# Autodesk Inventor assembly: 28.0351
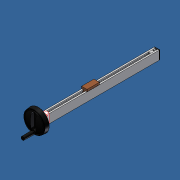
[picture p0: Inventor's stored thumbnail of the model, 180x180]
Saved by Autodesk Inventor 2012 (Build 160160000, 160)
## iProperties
Created: 2011-09
Part Number: 28.0351
Document SubType Name: Assembly
Designer: Administrator
Description: MINI ADJ UNIT 19X32
Author: Administrator
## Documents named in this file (8)
- C:\Andys Backup Data\ANDY'S INVENTOR\INVENTOR LIBRARIES\PARTS LIBRARY\READY FOR USE MODULES LG\28.0351 MINI ADJ UNIT 19X32.iam
- C:\Andys Backup Data\ANDY'S INVENTOR\INVENTOR LIBRARIES\PARTS LIBRARY\FASTENING ELEMENTS\SCREWS CAP\21.1200 M8X16.ipt
- C:\Andys Backup Data\ANDY'S INVENTOR\INVENTOR LIBRARIES\PARTS LIBRARY\READY FOR USE MODULES LG\28.0350 MINI ADJ UNIT FITTING KIT.iam
- C:\Andys Backup Data\ANDY'S INVENTOR\INVENTOR LIBRARIES\PARTS LIBRARY\READY FOR USE MODULES LG\SUBCOMPONENTS\28.0212 HANDWHEEL 80mm.iam
- C:\Andys Backup Data\ANDY'S INVENTOR\INVENTOR LIBRARIES\PARTS LIBRARY\READY FOR USE MODULES LG\SUBCOMPONENTS\19.0100_6 BUSHING.ipt
- C:\Andys Backup Data\ANDY'S INVENTOR\INVENTOR LIBRARIES\PARTS LIBRARY\READY FOR USE MODULES LG\SUBCOMPONENTS\28.0365 MINI ADJ BEARING SUPPORT 19X32.ipt
- C:\Andys Backup Data\ANDY'S INVENTOR\INVENTOR LIBRARIES\PARTS LIBRARY\READY FOR USE MODULES LG\SUBCOMPONENTS\28.0351_1 MINI ADJ 19X32 PROFILE.ipt
- C:\Andys Backup Data\ANDY'S INVENTOR\INVENTOR LIBRARIES\PARTS LIBRARY\END CAPS\22.1060_1 END CAP 19X32 GRAY.ipt
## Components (7 placed, 7 different names)
1. 21.1200 M8 x 16:1 — Insert:1
2. 28.0350 MINI ADJ UNIT FITTING KIT:1 [sub-assembly] — Mate:5, Mate:8, Angle:4, Insert:2
3. 28.0212 HANDWHEEL 80mm:1 [sub-assembly] — Mate:5, Angle:2, Mate:6, Mate:7
4. 19.0100_6 BUSHING:1 — Angle:2, Mate:6, Mate:7, Mate:8
5. 28.0365 MINI ADJ BEARING SUPPORT 19X32:1 — Mate:11, Mate:12, Angle:3, Insert:1, Insert:2
6. 28.0351_1 MINI ADJ 19X32 PROFILE:1 — Mate:9, Flush:1, Mate:10, Mate:11, Mate:12, Angle:3, Angle:4, Insert:3, Angle:5
7. 22.1060_1 END CAP 19X32 GRAY:1 — Insert:3, Angle:5
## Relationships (16: Mate 8, Angle 4, Insert 3, Flush 1)
- Mate:5: 28.0350 MINI ADJ UNIT FITTING KIT:1 ↔ 28.0212 HANDWHEEL 80mm:1
- Angle:2: 28.0212 HANDWHEEL 80mm:1 ↔ 19.0100_6 BUSHING:1
- Mate:6: 28.0212 HANDWHEEL 80mm:1 ↔ 19.0100_6 BUSHING:1
- Mate:7: 28.0212 HANDWHEEL 80mm:1 ↔ 19.0100_6 BUSHING:1
- Mate:8: 28.0350 MINI ADJ UNIT FITTING KIT:1 ↔ 19.0100_6 BUSHING:1
- Mate:9: 28.0351_1 MINI ADJ 19X32 PROFILE:1
- Flush:1: 28.0351_1 MINI ADJ 19X32 PROFILE:1
- Mate:10: 28.0351_1 MINI ADJ 19X32 PROFILE:1
- Mate:11: 28.0365 MINI ADJ BEARING SUPPORT 19X32:1 ↔ 28.0351_1 MINI ADJ 19X32 PROFILE:1
- Mate:12: 28.0365 MINI ADJ BEARING SUPPORT 19X32:1 ↔ 28.0351_1 MINI ADJ 19X32 PROFILE:1
- Angle:3: 28.0365 MINI ADJ BEARING SUPPORT 19X32:1 ↔ 28.0351_1 MINI ADJ 19X32 PROFILE:1
- Insert:1: 21.1200 M8 x 16:1 ↔ 28.0365 MINI ADJ BEARING SUPPORT 19X32:1
- Angle:4: 28.0350 MINI ADJ UNIT FITTING KIT:1 ↔ 28.0351_1 MINI ADJ 19X32 PROFILE:1
- Insert:2: 28.0350 MINI ADJ UNIT FITTING KIT:1 ↔ 28.0365 MINI ADJ BEARING SUPPORT 19X32:1
- Insert:3: 28.0351_1 MINI ADJ 19X32 PROFILE:1 ↔ 22.1060_1 END CAP 19X32 GRAY:1
- Angle:5: 28.0351_1 MINI ADJ 19X32 PROFILE:1 ↔ 22.1060_1 END CAP 19X32 GRAY:1
